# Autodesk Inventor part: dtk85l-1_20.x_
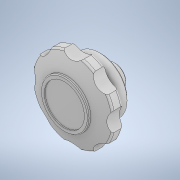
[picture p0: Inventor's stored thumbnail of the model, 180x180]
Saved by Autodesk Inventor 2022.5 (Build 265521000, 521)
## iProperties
Created: 2023-06
Part Number: dtk85l-1_20.x_
Material: Generic
Document SubType Name: Modeling
Designer: ImaoCorp
Density: 1 g/cm^3
Appearance: Default
Sending System: SOLIDWORKS 2021-2021301
MC: AMD64
MC_MODEL: Intel64 Family 6 Model 60 Stepping 3, GenuineIntel
OS: Windows_NT
FRU: Parasolid Version 32.1, build 255,  1- 1-2021
FORMAT: text
GUISE: transmit
KEY: dtk85l-1_20
FILE: dtk85l-1_20.x_t
DATE: Thu Jun 15 15:47:43 2023
Author: ImaoCorp
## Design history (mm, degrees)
feature "Base1"
node "ソリッド1"
